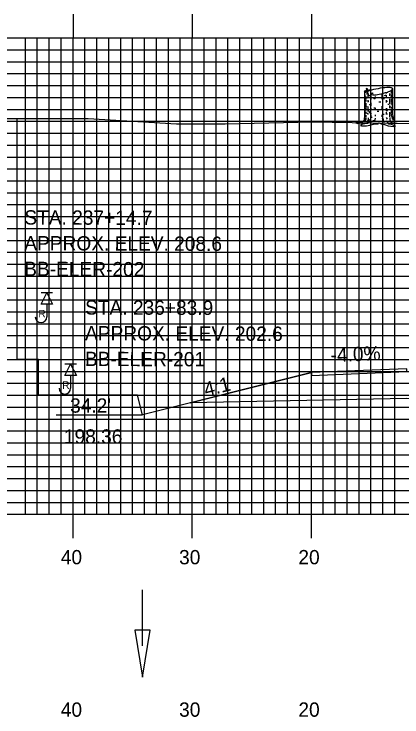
# Model space of a CAD drawing. Extents: x 1800749 to 1801092, y 442591 to 442811.
# Drawn here: x 1800869.6 to 1800902.1, y 442711.6 to 442770.7 of the extents above; entities that cross this region are included whole.
import ezdxf

# ---------------------------------------------------------------- set-up
doc = ezdxf.new("R2010")
doc.units = 0
for name, color, linetype in [('ANNOTATION', 7, 'Continuous'), ('BORING - REFUSAL', 7, 'Continuous'), ('D_Drainage_Ditch_Line', 7, 'Continuous'), ('D_Roadway_Edge_Shoulder', 7, 'Continuous'), ('D_Roadway_SlopeLines', 7, 'Continuous'), ('D_Roadway_SubGrade', 7, 'Continuous'), ('H_V ANNOTATION', 7, 'Continuous'), ('MAJOR', 7, 'Continuous'), ('MINOR', 7, 'Continuous'), ('PDRAIN', 7, 'Continuous'), ('S_Roadway_Centerline', 7, 'Continuous'), ('S_Trees_Decid_Pay', 7, 'Continuous')]:
    doc.layers.add(name, color=color, linetype=linetype)

msp = doc.modelspace()

# ---------------------------------------------------------------- linework, layer by layer
at = {"layer": 'ANNOTATION'}
for p, q in [((1800869.849, 442741.665), (1800869.849, 442761.907)), ((1800871.649, 442741.665), (1800869.849, 442741.665)), ((1800871.649, 442738.665), (1800871.649, 442741.665)), ((1800879.966, 442738.665), (1800871.649, 442738.665)), ((1800880.375, 442737.027), (1800879.966, 442738.665))]:
    msp.add_line(p, q, dxfattribs=at)
at = {"layer": 'BORING - REFUSAL'}
for p, q in [((1800872.829, 442747.265), (1800871.869, 442747.265)), ((1800872.349, 442746.306), (1800872.349, 442745.247)), ((1800874.829, 442741.265), (1800873.869, 442741.265)), ((1800874.349, 442740.306), (1800874.349, 442739.247))]:
    msp.add_line(p, q, dxfattribs=at)
for points in [[(1800872.349, 442747.265), (1800872.829, 442746.306), (1800871.869, 442746.306)], [(1800874.349, 442741.265), (1800874.829, 442740.306), (1800873.869, 442740.306)]]:
    msp.add_lwpolyline(points, close=True, dxfattribs=at)
for centre in [(1800871.864, 442745.247), (1800873.864, 442739.247)]:
    msp.add_arc(centre, 0.485, 180, 0, dxfattribs=at)
at = {"layer": 'D_Drainage_Ditch_Line'}
msp.add_line((1800880.376, 442717.626), (1800880.376, 442722.325), dxfattribs=at)
msp.add_lwpolyline([(1800881.032, 442718.939), (1800879.72, 442718.939), (1800880.376, 442715.002)], close=True, dxfattribs=at)
at = {"layer": 'D_Roadway_Edge_Shoulder'}
msp.add_lwpolyline([(1800902.549, 442740.891), (1800894.549, 442740.571), (1800894.549, 442740.321), (1800902.549, 442740.641)], close=True, dxfattribs=at)
at = {"layer": 'D_Roadway_SlopeLines'}
msp.add_lwpolyline([(1800894.549, 442740.571), (1800880.375, 442737.027)], dxfattribs=at)
at = {"layer": 'D_Roadway_SubGrade'}
msp.add_lwpolyline([(1800902.549, 442738.391), (1800884.375, 442738.027), (1800894.549, 442740.571), (1800894.549, 442740.321), (1800902.549, 442740.641), (1800914.549, 442740.401), (1800926.549, 442740.161), (1800934.549, 442739.841), (1800934.549, 442740.091), (1800944.723, 442737.547), (1800926.549, 442737.911), (1800914.549, 442738.151)], close=True, dxfattribs=at)
at = {"layer": 'MAJOR'}
for p, q in [((1800874.549, 442770.669), (1800874.549, 442768.665)), ((1800884.549, 442770.669), (1800884.549, 442768.665)), ((1800894.549, 442770.669), (1800894.549, 442768.665)), ((1800774.549, 442768.665), (1801054.549, 442768.665)), ((1800774.549, 442768.665), (1801054.549, 442768.665)), ((1800874.549, 442728.665), (1800874.549, 442768.665)), ((1800884.549, 442728.665), (1800884.549, 442768.665)), ((1800894.549, 442728.665), (1800894.549, 442768.665)), ((1800774.549, 442763.665), (1801054.549, 442763.665)), ((1800774.549, 442758.665), (1801054.549, 442758.665)), ((1800774.549, 442753.665), (1801054.549, 442753.665)), ((1800774.549, 442748.665), (1801054.549, 442748.665)), ((1800774.549, 442743.665), (1801054.549, 442743.665)), ((1800774.549, 442738.665), (1801054.549, 442738.665)), ((1800774.549, 442733.665), (1801054.549, 442733.665)), ((1800774.549, 442728.665), (1801054.549, 442728.665)), ((1800774.549, 442728.665), (1801054.549, 442728.665)), ((1800874.549, 442726.661), (1800874.549, 442728.665)), ((1800884.549, 442726.661), (1800884.549, 442728.665)), ((1800894.549, 442726.661), (1800894.549, 442728.665))]:
    msp.add_line(p, q, dxfattribs=at)
at = {"layer": 'MINOR'}
for p, q in [((1800870.549, 442728.665), (1800870.549, 442768.665)), ((1800871.549, 442728.665), (1800871.549, 442768.665)), ((1800872.549, 442728.665), (1800872.549, 442768.665)), ((1800873.549, 442728.665), (1800873.549, 442768.665)), ((1800875.549, 442728.665), (1800875.549, 442768.665)), ((1800876.549, 442728.665), (1800876.549, 442768.665)), ((1800877.549, 442728.665), (1800877.549, 442768.665)), ((1800878.549, 442728.665), (1800878.549, 442768.665)), ((1800879.549, 442728.665), (1800879.549, 442768.665)), ((1800880.549, 442728.665), (1800880.549, 442768.665)), ((1800881.549, 442728.665), (1800881.549, 442768.665)), ((1800882.549, 442728.665), (1800882.549, 442768.665)), ((1800883.549, 442728.665), (1800883.549, 442768.665)), ((1800885.549, 442728.665), (1800885.549, 442768.665)), ((1800886.549, 442728.665), (1800886.549, 442768.665)), ((1800887.549, 442728.665), (1800887.549, 442768.665)), ((1800888.549, 442728.665), (1800888.549, 442768.665)), ((1800889.549, 442728.665), (1800889.549, 442768.665)), ((1800890.549, 442728.665), (1800890.549, 442768.665)), ((1800891.549, 442728.665), (1800891.549, 442768.665)), ((1800892.549, 442728.665), (1800892.549, 442768.665)), ((1800893.549, 442728.665), (1800893.549, 442768.665)), ((1800895.549, 442728.665), (1800895.549, 442768.665)), ((1800896.549, 442728.665), (1800896.549, 442768.665)), ((1800897.549, 442728.665), (1800897.549, 442768.665)), ((1800898.549, 442728.665), (1800898.549, 442768.665)), ((1800899.549, 442728.665), (1800899.549, 442768.665)), ((1800900.549, 442728.665), (1800900.549, 442768.665)), ((1800901.549, 442728.665), (1800901.549, 442768.665)), ((1800774.549, 442767.665), (1801054.549, 442767.665)), ((1800774.549, 442766.665), (1801054.549, 442766.665)), ((1800774.549, 442765.665), (1801054.549, 442765.665)), ((1800774.549, 442764.665), (1801054.549, 442764.665)), ((1800774.549, 442762.665), (1801054.549, 442762.665)), ((1800774.549, 442761.665), (1801054.549, 442761.665)), ((1800774.549, 442760.665), (1801054.549, 442760.665)), ((1800774.549, 442759.665), (1801054.549, 442759.665)), ((1800774.549, 442757.665), (1801054.549, 442757.665)), ((1800774.549, 442756.665), (1801054.549, 442756.665)), ((1800774.549, 442755.665), (1801054.549, 442755.665)), ((1800774.549, 442754.665), (1801054.549, 442754.665)), ((1800774.549, 442752.665), (1801054.549, 442752.665)), ((1800774.549, 442751.665), (1801054.549, 442751.665)), ((1800774.549, 442750.665), (1801054.549, 442750.665)), ((1800774.549, 442749.665), (1801054.549, 442749.665)), ((1800774.549, 442747.665), (1801054.549, 442747.665)), ((1800774.549, 442746.665), (1801054.549, 442746.665)), ((1800774.549, 442745.665), (1801054.549, 442745.665)), ((1800774.549, 442744.665), (1801054.549, 442744.665)), ((1800774.549, 442742.665), (1801054.549, 442742.665)), ((1800774.549, 442741.665), (1801054.549, 442741.665)), ((1800774.549, 442740.665), (1801054.549, 442740.665)), ((1800774.549, 442739.665), (1801054.549, 442739.665)), ((1800774.549, 442737.665), (1801054.549, 442737.665)), ((1800774.549, 442736.665), (1801054.549, 442736.665)), ((1800774.549, 442735.665), (1801054.549, 442735.665)), ((1800774.549, 442734.665), (1801054.549, 442734.665)), ((1800774.549, 442732.665), (1801054.549, 442732.665)), ((1800774.549, 442731.665), (1801054.549, 442731.665)), ((1800774.549, 442730.665), (1801054.549, 442730.665)), ((1800774.549, 442729.665), (1801054.549, 442729.665))]:
    msp.add_line(p, q, dxfattribs=at)
at = {"layer": 'PDRAIN'}
msp.add_line((1800873.142, 442737.027), (1800880.375, 442737.027), dxfattribs=at)
at = {"layer": 'S_Roadway_Centerline'}
msp.add_lwpolyline([(1800866.1, 442761.904), (1800875.807, 442761.911), (1800883.239, 442761.453), (1800885.214, 442761.45), (1800887.306, 442761.449), (1800894.628, 442761.623), (1800904.587, 442761.45), (1800913.116, 442761.584), (1800929.195, 442761.256), (1800930.25, 442761.216), (1800931.784, 442761.218), (1800942.325, 442761.297), (1800947.724, 442761.167), (1800953.393, 442761.434), (1800961.402, 442761.623), (1800969.813, 442761.349), (1800978.864, 442761.572), (1800980.005, 442761.672), (1800982.683, 442761.738), (1801004.152, 442760.964)], dxfattribs=at)
at = {"layer": 'S_Trees_Decid_Pay'}
for p, q in [((1800899.193, 442764.093), (1800899.193, 442763.919)), ((1800900.832, 442764.085), (1800900.832, 442763.999)), ((1800901.105, 442763.999), (1800901.105, 442763.807)), ((1800901.237, 442764.252), (1800901.237, 442763.999)), ((1800901.317, 442764.297), (1800901.317, 442764.176)), ((1800901.317, 442764.124), (1800901.317, 442763.91)), ((1800899.043, 442763.893), (1800899.043, 442763.639)), ((1800899.043, 442763.542), (1800899.043, 442763.072)), ((1800899.129, 442763.748), (1800899.129, 442763.536)), ((1800899.129, 442763.47), (1800899.129, 442763.322)), ((1800899.277, 442763.845), (1800899.277, 442763.64)), ((1800899.277, 442763.433), (1800899.277, 442763.278)), ((1800899.539, 442763.847), (1800899.539, 442763.727)), ((1800899.539, 442763.675), (1800899.539, 442763.49)), ((1800899.777, 442763.575), (1800899.782, 442763.682)), ((1800899.903, 442763.748), (1800899.903, 442763.568)), ((1800900.449, 442763.984), (1800900.449, 442763.704)), ((1800900.449, 442763.639), (1800900.449, 442763.536)), ((1800900.832, 442763.858), (1800900.832, 442763.719)), ((1800900.832, 442763.433), (1800900.832, 442763.241)), ((1800901.105, 442763.556), (1800901.105, 442763.278)), ((1800901.237, 442763.902), (1800901.237, 442763.639)), ((1800901.237, 442763.542), (1800901.237, 442763.233)), ((1800901.317, 442763.865), (1800901.317, 442763.527)), ((1800901.317, 442763.41), (1800901.317, 442763.049)), ((1800899.043, 442763.021), (1800899.043, 442762.887)), ((1800899.043, 442762.83), (1800899.043, 442762.504)), ((1800899.129, 442763.145), (1800899.129, 442762.844)), ((1800899.277, 442762.916), (1800899.277, 442762.696)), ((1800899.539, 442763.204), (1800899.539, 442762.976)), ((1800900.449, 442762.924), (1800900.449, 442762.704)), ((1800901.105, 442763.233), (1800901.105, 442763.124)), ((1800901.105, 442762.99), (1800901.105, 442762.761)), ((1800901.237, 442763.145), (1800901.237, 442763.078)), ((1800901.237, 442762.844), (1800901.237, 442762.747)), ((1800901.317, 442763.013), (1800901.317, 442762.564)), ((1800899.043, 442762.475), (1800899.043, 442762.055)), ((1800899.129, 442762.807), (1800899.129, 442762.564)), ((1800899.129, 442762.453), (1800899.129, 442762.313)), ((1800899.277, 442762.596), (1800899.277, 442762.475)), ((1800899.277, 442762.324), (1800899.277, 442762.226)), ((1800899.539, 442762.778), (1800899.539, 442762.593)), ((1800899.539, 442762.358), (1800899.539, 442762.281)), ((1800899.903, 442762.79), (1800899.903, 442762.593)), ((1800900.832, 442762.761), (1800900.832, 442762.553)), ((1800900.832, 442762.432), (1800900.832, 442762.232)), ((1800901.105, 442762.432), (1800901.105, 442762.049)), ((1800901.237, 442762.696), (1800901.237, 442762.335)), ((1800901.237, 442762.284), (1800901.237, 442762.117)), ((1800901.317, 442762.498), (1800901.317, 442762.216)), ((1800899.046, 442761.952), (1800899.032, 442761.835)), ((1800899.129, 442762.181), (1800899.129, 442762.024)), ((1800899.539, 442762.204), (1800899.539, 442762.03)), ((1800899.903, 442762.209), (1800899.903, 442762.106)), ((1800900.449, 442762.204), (1800900.449, 442762.03)), ((1800900.828, 442761.975), (1800900.908, 442761.843))]:
    msp.add_line(p, q, dxfattribs=at)
for points in [[(1800898.993, 442764.167), (1800898.993, 442762.03), (1800898.972, 442761.889), (1800898.966, 442761.763), (1800898.923, 442761.676), (1800898.831, 442761.627), (1800898.695, 442761.627), (1800898.451, 442761.571), (1800898.285, 442761.522), (1800898.427, 442761.491), (1800898.664, 442761.528), (1800898.874, 442761.516), (1800899.135, 442761.522), (1800899.259, 442761.54), (1800899.289, 442761.498), (1800899.352, 442761.54), (1800899.252, 442761.473), (1800899.018, 442761.448), (1800898.787, 442761.386), (1800898.657, 442761.316), (1800898.756, 442761.272), (1800899.178, 442761.292), (1800899.457, 442761.335), (1800899.755, 442761.411), (1800900.041, 442761.448), (1800900.146, 442761.448), (1800900.165, 442761.528), (1800900.233, 442761.534), (1800900.399, 442761.448), (1800900.686, 442761.392), (1800900.984, 442761.285), (1800901.443, 442761.236), (1800901.598, 442761.248), (1800901.256, 442761.398), (1800901.052, 442761.429), (1800901.064, 442761.503), (1800901.324, 442761.603), (1800901.499, 442761.633), (1800901.74, 442761.645), (1800901.542, 442761.683), (1800901.48, 442761.719), (1800901.456, 442761.806), (1800901.443, 442761.975), (1800901.398, 442762.061), (1800901.37, 442762.302), (1800901.37, 442764.388)], [(1800899.349, 442763.84), (1800899.341, 442763.984), (1800899.296, 442763.977), (1800899.281, 442764.351), (1800899.187, 442764.359), (1800899.172, 442764.439), (1800899.135, 442764.102), (1800899.09, 442764.196), (1800899.069, 442764.042), (1800898.993, 442764.167), (1800898.998, 442763.978)], [(1800898.993, 442764.167), (1800899.039, 442764.19), (1800899.061, 442764.256), (1800899.113, 442764.279), (1800899.146, 442764.204)], [(1800899.371, 442764.206), (1800899.392, 442764.314), (1800899.524, 442764.345), (1800899.531, 442764.257)], [(1800899.51, 442763.845), (1800899.547, 442763.948), (1800899.613, 442763.954), (1800899.613, 442764.036), (1800899.687, 442764.042), (1800899.712, 442763.862)], [(1800899.401, 442762.475), (1800899.392, 442762.401), (1800899.466, 442762.395), (1800899.481, 442762.512)], [(1800900.946, 442762.567), (1800900.945, 442762.644), (1800900.937, 442762.71)], [(1800899.113, 442761.96), (1800899.106, 442761.835), (1800899.024, 442761.74)], [(1800899.259, 442761.54), (1800899.277, 442761.719), (1800899.339, 442761.856), (1800899.332, 442761.956)], [(1800899.45, 442761.788), (1800899.376, 442761.719), (1800899.357, 442761.621), (1800899.352, 442761.54)], [(1800899.901, 442761.923), (1800899.884, 442761.769), (1800899.687, 442761.688), (1800899.642, 442761.585)], [(1800900.467, 442761.915), (1800900.57, 442761.864), (1800900.584, 442761.658), (1800900.687, 442761.629)], [(1800901.052, 442761.429), (1800900.966, 442761.571), (1800900.834, 442761.713)], [(1800901.122, 442761.989), (1800901.122, 442761.784), (1800901.18, 442761.674), (1800901.277, 442761.658)], [(1800901.262, 442762.063), (1800901.334, 442761.96), (1800901.334, 442761.835)], [(1800901.319, 442762.144), (1800901.38, 442761.983), (1800901.394, 442761.858), (1800901.386, 442761.761)]]:
    msp.add_lwpolyline(points, dxfattribs=at)
for centre, radius, start, end in [((1800899.802, 442762.98), 1.299, 107.86134, 113.3069), ((1800901.283, 442758.386), 6.126, 100.77788, 107.86134), ((1800901.283, 442758.386), 6.126, 93.69441, 100.77788), ((1800899.08, 442769.955), 6.126, 280.77788, 287.86134), ((1800900.972, 442763.203), 1.299, 78.27788, 93.69441), ((1800900.561, 442765.361), 1.299, 287.86134, 303.27788), ((1800901.138, 442764.006), 0.48, 69.98432, 78.27788), ((1800901.011, 442764.676), 0.48, 303.27788, 311.57144), ((1800901.246, 442764.302), 0.164, 55.77788, 69.98432), ((1800901.23, 442764.131), 0.166, 301.67004, 315), ((1800901.22, 442764.44), 0.164, 311.57144, 325.77788), ((1800901.278, 442764.349), 0.107, 45.9547, 55.77788), ((1800901.271, 442764.09), 0.109, 315, 324.82628), ((1800901.308, 442764.38), 0.0645, 33.27788, 45.9547), ((1800901.267, 442764.408), 0.107, 325.77788, 335.60106), ((1800901.306, 442764.065), 0.0657, 324.82628, 337.5), ((1800901.316, 442764.385), 0.0544, 22.46002, 33.27788), ((1800901.306, 442764.39), 0.0645, 335.60106, 348.27788), ((1800901.323, 442764.388), 0.0467, 10.77788, 22.46002), ((1800901.316, 442764.062), 0.0554, 337.5, 348.31854), ((1800901.323, 442764.388), 0.0467, 359.09574, 10.77788), ((1800901.316, 442764.388), 0.0544, 348.27788, 359.09574), ((1800899.04, 442763.799), 0.0476, 180, 191.68146), ((1800899.048, 442763.801), 0.0554, 191.68146, 202.5), ((1800899.058, 442763.805), 0.0657, 202.5, 215.17372), ((1800899.093, 442763.83), 0.109, 215.17372, 225), ((1800899.134, 442763.87), 0.166, 225, 239.19244), ((1800899.134, 442763.607), 0.166, 237.03779, 239.19244), ((1800899.296, 442763.88), 0.484, 239.19244, 247.5), ((1800899.606, 442764.626), 1.292, 247.5, 248.35373), ((1800899.606, 442764.889), 1.292, 250.61187, 255.28558), ((1800899.391, 442765.139), 1.299, 268.12894, 273.69441), ((1800899.08, 442769.955), 6.126, 273.69441, 274.02462), ((1800899.08, 442769.955), 6.126, 275.91473, 280.77788), ((1800900.181, 442769.477), 5.916, 266.07764, 267.30434), ((1800900.181, 442769.477), 5.916, 273.53821, 274.89239), ((1800900.182, 442769.738), 5.916, 274.95145, 276.30875), ((1800900.758, 442765.15), 1.292, 285.56513, 289.09156), ((1800900.757, 442764.889), 1.292, 288.08294, 292.5), ((1800900.757, 442764.626), 1.292, 291.8071, 292.5), ((1800901.066, 442763.88), 0.484, 292.5, 300.80756), ((1800901.066, 442764.143), 0.484, 297.41617, 300.80756), ((1800901.229, 442763.87), 0.166, 300.80756, 315), ((1800901.229, 442763.607), 0.166, 300.80756, 301.6001), ((1800901.27, 442763.83), 0.109, 315, 324.82628), ((1800901.305, 442763.805), 0.0657, 324.82628, 337.5), ((1800901.315, 442763.801), 0.0554, 337.5, 348.31854), ((1800899.04, 442763.278), 0.0476, 180, 191.68146), ((1800899.04, 442763.021), 0.0476, 180, 191.68146), ((1800899.048, 442763.28), 0.0554, 191.68146, 202.5), ((1800899.048, 442763.022), 0.0554, 191.68146, 202.5), ((1800899.058, 442763.284), 0.0657, 202.5, 215.17372), ((1800899.058, 442763.026), 0.0657, 202.5, 215.17372), ((1800899.093, 442763.309), 0.109, 215.17372, 225), ((1800899.093, 442763.051), 0.109, 215.17372, 225), ((1800899.134, 442763.349), 0.166, 225, 239.19244), ((1800899.134, 442763.092), 0.166, 225, 239.19244), ((1800899.296, 442763.622), 0.484, 239.19244, 245.77245), ((1800899.606, 442764.369), 1.292, 247.5, 248.48417), ((1800899.606, 442764.111), 1.292, 247.5, 251.79898), ((1800899.606, 442764.626), 1.292, 255.28558, 259.26323), ((1800899.606, 442764.369), 1.292, 261.87258, 262.84538), ((1800900.181, 442768.956), 5.916, 262.84537, 263.7595), ((1800900.181, 442769.214), 5.916, 270.1162, 271.77083), ((1800900.181, 442769.214), 5.916, 276.31835, 277.15463), ((1800900.757, 442764.626), 1.292, 277.15463, 278.36619), ((1800900.757, 442764.369), 1.292, 279.25654, 285.6105), ((1800900.757, 442764.111), 1.292, 285.61049, 290.10015), ((1800901.066, 442763.622), 0.484, 294.63721, 300.80756), ((1800901.229, 442763.349), 0.166, 300.80756, 315), ((1800901.229, 442763.092), 0.166, 302.06939, 315), ((1800901.27, 442763.309), 0.109, 315, 324.82628), ((1800901.27, 442763.051), 0.109, 315, 324.82628), ((1800901.305, 442763.284), 0.0657, 324.82628, 337.5), ((1800901.305, 442763.026), 0.0657, 324.82628, 337.5), ((1800901.315, 442763.28), 0.0554, 337.5, 348.31854), ((1800901.315, 442763.022), 0.0554, 337.5, 348.31854), ((1800899.04, 442762.755), 0.0476, 180, 191.68146), ((1800899.04, 442762.226), 0.0476, 180, 191.68146), ((1800899.048, 442762.757), 0.0554, 191.68146, 202.5), ((1800899.058, 442762.761), 0.0657, 202.5, 215.17372), ((1800899.093, 442762.786), 0.109, 215.17372, 225), ((1800899.134, 442762.826), 0.166, 225, 239.19244), ((1800899.296, 442763.099), 0.484, 239.19244, 247.5), ((1800899.296, 442762.827), 0.484, 242.73401, 247.5), ((1800899.606, 442763.846), 1.292, 247.5, 248.35373), ((1800899.606, 442763.574), 1.292, 251.36642, 255.28558), ((1800899.606, 442763.846), 1.292, 255.28558, 259.24628), ((1800900.181, 442768.699), 5.916, 266.27211, 267.30434), ((1800900.181, 442768.434), 5.916, 268.92065, 270), ((1800900.181, 442768.434), 5.916, 270, 270.27568), ((1800900.181, 442768.162), 5.916, 273.26366, 274.46102), ((1800900.181, 442768.434), 5.916, 276.31835, 277.15463), ((1800900.181, 442768.162), 5.916, 276.31835, 277.15463), ((1800900.757, 442763.846), 1.292, 277.15463, 278.37952), ((1800900.757, 442763.574), 1.292, 277.15463, 278.36619), ((1800900.757, 442763.574), 1.292, 285.61049, 289.15336), ((1800901.066, 442763.099), 0.484, 292.5, 300.80756), ((1800901.229, 442762.826), 0.166, 300.80756, 302.06939), ((1800901.229, 442762.555), 0.166, 302.06939, 315), ((1800901.27, 442762.514), 0.109, 315, 324.82628), ((1800901.305, 442762.489), 0.0657, 324.82628, 337.5), ((1800901.315, 442762.757), 0.0554, 337.5, 348.31854), ((1800901.315, 442762.485), 0.0554, 337.5, 348.31854), ((1800899.048, 442762.228), 0.0554, 191.68146, 202.5), ((1800899.058, 442762.232), 0.0657, 202.5, 215.17372), ((1800899.093, 442762.257), 0.109, 215.17372, 225), ((1800899.134, 442762.297), 0.166, 225, 239.19244), ((1800899.296, 442762.57), 0.484, 239.19244, 247.5), ((1800899.606, 442763.316), 1.292, 247.5, 248.35373), ((1800900.181, 442767.904), 5.916, 263.78314, 264.76555), ((1800900.767, 442763.32), 1.292, 291.36963, 292.0604), ((1800901.066, 442762.57), 0.484, 292.5, 296.54992)]:
    msp.add_arc(centre, radius, start, end, dxfattribs=at)

# ---------------------------------------------------------------- texts
at = {"layer": 'ANNOTATION'}
for s, rotation, p in [('-4.0%', 2.29061, (1800896.181, 442741.438)), ('4:1', 14.03624, (1800885.695, 442738.537))]:
    msp.add_text(s, height=1.2, rotation=rotation, dxfattribs=at).set_placement(p)
for s, p in [("34.2'", (1800874.304, 442737.198)), ('198.36', (1800873.784, 442734.598))]:
    msp.add_text(s, height=1.2, dxfattribs=at).set_placement(p)
at = {"layer": 'BORING - REFUSAL'}
for s, p in [('STA. 237+14.7', (1800870.462, 442752.995)), ('APPROX. ELEV. 208.6', (1800870.455, 442750.835)), ('BB-ELER-202', (1800870.448, 442748.675)), ('STA. 236+83.9', (1800875.56, 442745.437)), ('APPROX. ELEV. 202.6', (1800875.553, 442743.277)), ('BB-ELER-201', (1800875.546, 442741.117))]:
    msp.add_text(s, height=1.2, rotation=359.81416, dxfattribs=at).set_placement(p)
for p in [(1800871.64, 442745.191), (1800873.64, 442739.191)]:
    msp.add_text('R', height=0.64, dxfattribs=at).set_placement(p)
at = {"layer": 'H_V ANNOTATION'}
for s, p in [('40', (1800873.522, 442724.465)), ('30', (1800883.447, 442724.465)), ('20', (1800893.457, 442724.465)), ('40', (1800873.522, 442711.665)), ('30', (1800883.447, 442711.665)), ('20', (1800893.457, 442711.665))]:
    msp.add_text(s, height=1.2, dxfattribs=at).set_placement(p)

doc.saveas('drawing.dxf')
